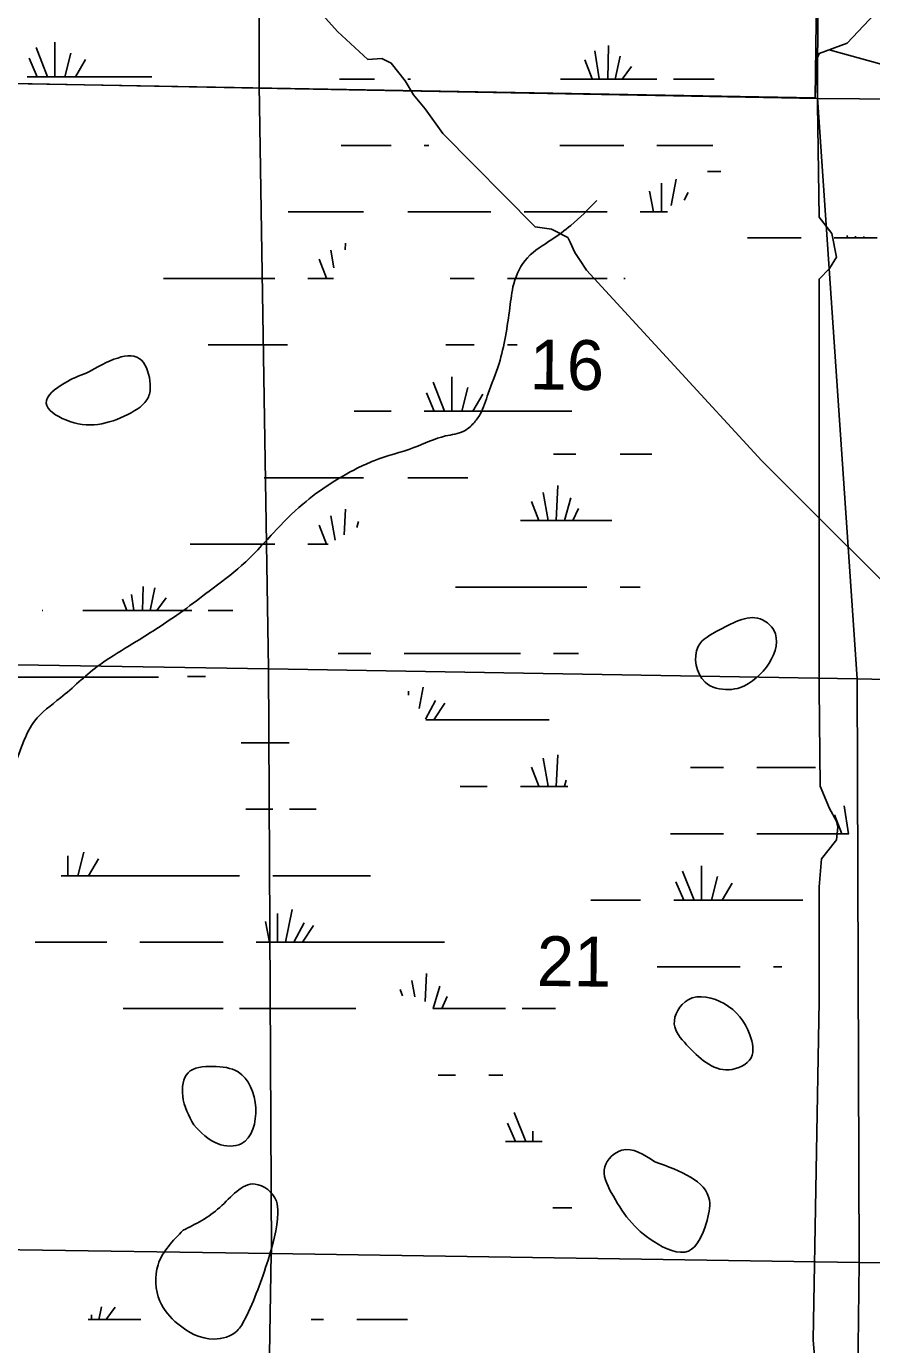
# Model space of a CAD drawing. Extents: x 408847 to 817539, y 923858 to 1151780.
# Drawn here: x 582458 to 590088, y 1023095 to 1034999 of the extents above; entities that cross this region are included whole.
import ezdxf

# ---------------------------------------------------------------- set-up
doc = ezdxf.new("R2010")
doc.units = 0
for name, color, linetype in [('Lakes and Ponds', 7, 'Continuous'), ('Level 43', 7, 'Continuous'), ('Local Roads Paved', 7, 'Continuous'), ('Narrow River Creek and Branch and Slough', 7, 'Continuous'), ('Section Lines', 7, 'Continuous'), ('State Park', 7, 'Continuous'), ('Swamps', 7, 'Continuous')]:
    doc.layers.add(name, color=color, linetype=linetype)

msp = doc.modelspace()

# ---------------------------------------------------------------- linework, layer by layer
at = {"layer": 'Lakes and Ponds'}
for points in [[(582997, 1031866), (582802, 1031778), (582636, 1031597), (582813, 1031445), (583375, 1031495), (583559, 1031651), (583576, 1031767), (583497, 1031983), (582997, 1031866)], [(588714, 1029548), (588522, 1029398), (588585, 1029077), (588798, 1029010), (588904, 1029029), (589204, 1029547), (589103, 1029640), (588714, 1029548)], [(588417, 1025803), (588801, 1025577), (589000, 1025685), (588990, 1025893), (588757, 1026174), (588431, 1026208), (588307, 1025989), (588417, 1025803)], [(583968, 1025080), (584188, 1024908), (584398, 1024909), (584528, 1025232), (584369, 1025557), (584140, 1025607), (583917, 1025549), (583869, 1025340), (583968, 1025080)], [(588130, 1024747), (587833, 1024850), (587679, 1024699), (587738, 1024468), (588122, 1024025), (588435, 1023940), (588594, 1024189), (588624, 1024399), (588130, 1024747)], [(583874, 1024128), (583646, 1023816), (583663, 1023487), (583824, 1023283), (584151, 1023145), (584360, 1023219), (584431, 1023326), (584639, 1023859), (584727, 1024285), (584715, 1024391), (584522, 1024545), (584204, 1024334), (583874, 1024128)]]:
    msp.add_spline(points, degree=3, dxfattribs=at)
at = {"layer": 'Local Roads Paved'}
for points in [[(583335, 1036994), (583683, 1036592), (583820, 1036508), (583958, 1036392), (583979, 1036339), (584327, 1035927), (584591, 1035706), (585266, 1034951)], [(583335, 1036994), (583683, 1036592), (583820, 1036508), (583958, 1036392), (583979, 1036339), (584327, 1035927), (584591, 1035706), (585266, 1034951)], [(592653, 1035968), (592062, 1035904), (591809, 1035820), (591809, 1035820), (591714, 1035788), (590965, 1035598), (590447, 1035397), (590258, 1035334), (590215, 1035218), (589867, 1034848), (589614, 1034753), (589593, 1034701), (589614, 1033275), (589730, 1033127), (589772, 1032916), (589709, 1032811), (589614, 1032716), (589614, 1032705), (589614, 1029020)], [(585266, 1034951), (585541, 1034698), (585667, 1034708), (585752, 1034666), (585878, 1034508), (585952, 1034381), (586058, 1034254), (586216, 1034032), (587050, 1033188), (587197, 1033167), (587345, 1033093), (587366, 1033051), (587408, 1032956), (587451, 1032892), (587514, 1032797), (589097, 1031076), (590659, 1029517)], [(585266, 1034951), (585541, 1034698), (585667, 1034708), (585752, 1034666), (585878, 1034508), (585952, 1034381), (586058, 1034254), (586216, 1034032), (587050, 1033188), (587197, 1033167), (587345, 1033093), (587366, 1033051), (587408, 1032956), (587451, 1032892), (587514, 1032797), (589097, 1031076), (590659, 1029517)], [(589706, 1034788), (590785, 1034489), (591862, 1034215), (592664, 1033995)], [(589614, 1029020), (589624, 1028137), (589709, 1027937), (589772, 1027821), (589783, 1027768), (589772, 1027652), (589762, 1027641)], [(589762, 1027641), (589635, 1027483), (589614, 1027229), (589614, 1026195), (589561, 1023139), (589572, 1022991), (589614, 1022506)]]:
    msp.add_lwpolyline(points, dxfattribs=at)
at = {"layer": 'Narrow River Creek and Branch and Slough'}
msp.add_spline([(578344, 1023366), (578685, 1023341), (578962, 1023402), (579245, 1023485), (579500, 1023572), (579779, 1023651), (580004, 1023741), (580103, 1023850), (580238, 1024045), (580430, 1024259), (580618, 1024431), (580874, 1024657), (581386, 1025130), (581493, 1025235), (581636, 1025518), (581786, 1025867), (581935, 1026208), (582029, 1026506), (582096, 1026797), (582155, 1027119), (582238, 1027391), (582270, 1027751), (582295, 1027981), (582350, 1028297), (582439, 1028556), (582531, 1028724), (582765, 1028935), (583098, 1029218), (583387, 1029406), (583876, 1029725), (584108, 1029899), (584401, 1030130), (584686, 1030423), (584953, 1030685), (585197, 1030866), (585445, 1031008), (585595, 1031076), (585955, 1031195), (586242, 1031300), (586406, 1031344), (586493, 1031413), (586554, 1031497), (586626, 1031682), (586725, 1031954), (586782, 1032199), (586823, 1032461), (586857, 1032673), (586982, 1032910), (587201, 1033074), (587373, 1033201), (587607, 1033426)], degree=3, dxfattribs=at)
at = {"layer": 'Section Lines'}
for p, q in [((584560, 1034469), (584547, 1039763)), ((589612, 1039690), (589600, 1034348)), ((579273, 1034538), (584560, 1034441)), ((584560, 1034469), (584643, 1029196)), ((584560, 1034441), (589600, 1034348)), ((589600, 1034354), (589958, 1029106)), ((589600, 1034348), (594987, 1034298)), ((579348, 1029286), (584643, 1029196)), ((584643, 1029214), (584670, 1023921)), ((584643, 1029196), (589957, 1029106)), ((589957, 1029106), (589976, 1023836)), ((589958, 1029106), (595282, 1029016)), ((579371, 1023999), (584669, 1023917)), ((584669, 1023917), (584568, 1018625)), ((584669, 1023917), (589976, 1023836)), ((589976, 1023836), (589903, 1018532)), ((589976, 1023836), (595213, 1023756))]:
    msp.add_line(p, q, dxfattribs=at)
at = {"layer": 'State Park'}
msp.add_lwpolyline([(589721, 1045058), (589578, 1034352), (573671, 1034637), (573671, 1035240), (557880, 1035240)], dxfattribs=at)
at = {"layer": 'Swamps'}
for p, q in [((582545, 1034807), (582648, 1034544)), ((582545, 1034807), (582648, 1034544)), ((582545, 1034807), (582648, 1034544)), ((582714, 1034855), (582714, 1034544)), ((582714, 1034855), (582714, 1034544)), ((582714, 1034855), (582714, 1034544)), ((587707, 1034523), (587712, 1034827)), ((587707, 1034523), (587712, 1034827)), ((582484, 1034710), (582555, 1034544)), ((582484, 1034710), (582555, 1034544)), ((582484, 1034710), (582555, 1034544)), ((582859, 1034758), (582805, 1034544)), ((582859, 1034758), (582805, 1034544)), ((582859, 1034758), (582805, 1034544)), ((582992, 1034698), (582902, 1034544)), ((582992, 1034698), (582902, 1034544)), ((582992, 1034698), (582902, 1034544)), ((587566, 1034524), (587500, 1034697)), ((587566, 1034524), (587500, 1034697)), ((587628, 1034524), (587589, 1034777)), ((587628, 1034524), (587589, 1034777)), ((587774, 1034523), (587817, 1034729)), ((587774, 1034523), (587817, 1034729)), ((587836, 1034523), (587920, 1034637)), ((587836, 1034523), (587920, 1034637)), ((587400, 1034523), (588150, 1034523)), ((587400, 1034523), (588150, 1034523)), ((585300, 1033923), (585750, 1033923)), ((585300, 1033923), (585750, 1033923)), ((587400, 1033923), (587850, 1033923)), ((587400, 1033923), (587850, 1033923)), ((588083, 1033510), (588120, 1033323)), ((588083, 1033510), (588120, 1033323)), ((588191, 1033582), (588191, 1033323)), ((588191, 1033582), (588191, 1033323)), ((585900, 1033323), (586650, 1033323)), ((585900, 1033323), (586650, 1033323)), ((586950, 1033323), (587400, 1033323)), ((586950, 1033323), (587400, 1033323)), ((587400, 1033323), (587700, 1033323)), ((587400, 1033323), (587700, 1033323)), ((589151, 1033089), (589451, 1033089)), ((589151, 1033089), (589451, 1033089)), ((585166, 1032724), (585100, 1032895)), ((585166, 1032724), (585100, 1032895)), ((586800, 1032723), (587400, 1032723)), ((586800, 1032723), (587400, 1032723)), ((587400, 1032723), (587700, 1032723)), ((587400, 1032723), (587700, 1032723)), ((586299, 1031834), (586299, 1031523)), ((586299, 1031834), (586299, 1031523)), ((586130, 1031786), (586233, 1031523)), ((586130, 1031786), (586233, 1031523)), ((586444, 1031738), (586390, 1031523)), ((586444, 1031738), (586390, 1031523)), ((586069, 1031689), (586140, 1031523)), ((586069, 1031689), (586140, 1031523)), ((586577, 1031677), (586487, 1031524)), ((586577, 1031677), (586487, 1031524)), ((587168, 1030537), (587122, 1030791)), ((587168, 1030537), (587122, 1030791)), ((587168, 1030537), (587122, 1030791)), ((587239, 1030536), (587256, 1030853)), ((587239, 1030536), (587256, 1030853)), ((587239, 1030536), (587256, 1030853)), ((587083, 1030537), (587017, 1030709)), ((587083, 1030537), (587017, 1030709)), ((587083, 1030537), (587017, 1030709)), ((587316, 1030537), (587374, 1030740)), ((587316, 1030537), (587374, 1030740)), ((587316, 1030537), (587374, 1030740)), ((587392, 1030537), (587441, 1030645)), ((587392, 1030537), (587441, 1030645)), ((587392, 1030537), (587441, 1030645)), ((585166, 1030324), (585100, 1030495)), ((585166, 1030324), (585100, 1030495)), ((583574, 1029723), (583617, 1029929)), ((583574, 1029723), (583617, 1029929)), ((583636, 1029723), (583720, 1029837)), ((583636, 1029723), (583720, 1029837)), ((583200, 1029723), (583950, 1029723)), ((583200, 1029723), (583950, 1029723)), ((585867, 1029336), (586917, 1029336)), ((585867, 1029336), (586917, 1029336)), ((585867, 1029336), (586917, 1029336)), ((581850, 1029123), (583200, 1029123)), ((581850, 1029123), (583200, 1029123)), ((583200, 1029123), (583650, 1029123)), ((583200, 1029123), (583650, 1029123)), ((586234, 1028886), (586135, 1028737)), ((586234, 1028886), (586135, 1028737)), ((586234, 1028886), (586135, 1028737)), ((587168, 1028137), (587122, 1028391)), ((587168, 1028137), (587122, 1028391)), ((587168, 1028137), (587122, 1028391)), ((587083, 1028137), (587017, 1028309)), ((587083, 1028137), (587017, 1028309)), ((587083, 1028137), (587017, 1028309)), ((588452, 1028307), (588752, 1028307)), ((588452, 1028307), (588752, 1028307)), ((589880, 1027707), (589841, 1027960)), ((589880, 1027707), (589841, 1027960)), ((589818, 1027708), (589752, 1027880)), ((589818, 1027708), (589752, 1027880)), ((589052, 1027707), (589652, 1027707)), ((589052, 1027707), (589652, 1027707)), ((582976, 1027543), (582923, 1027329)), ((582976, 1027543), (582923, 1027329)), ((583109, 1027483), (583020, 1027329)), ((583109, 1027483), (583020, 1027329)), ((588551, 1027418), (588551, 1027107)), ((588551, 1027418), (588551, 1027107)), ((583933, 1027329), (584383, 1027329)), ((583933, 1027329), (584383, 1027329)), ((588382, 1027369), (588485, 1027107)), ((588382, 1027369), (588485, 1027107)), ((588696, 1027321), (588643, 1027107)), ((588696, 1027321), (588643, 1027107)), ((588322, 1027273), (588392, 1027107)), ((588322, 1027273), (588392, 1027107)), ((588829, 1027261), (588739, 1027107)), ((588829, 1027261), (588739, 1027107)), ((587552, 1027107), (588002, 1027107)), ((587552, 1027107), (588002, 1027107)), ((584724, 1026987), (584724, 1026729)), ((584724, 1026987), (584724, 1026729)), ((584857, 1027024), (584798, 1026729)), ((584857, 1027024), (584798, 1026729)), ((584615, 1026915), (584652, 1026729)), ((584615, 1026915), (584652, 1026729)), ((584965, 1026903), (584871, 1026728)), ((584965, 1026903), (584871, 1026728)), ((585050, 1026879), (584951, 1026730)), ((585050, 1026879), (584951, 1026730)), ((583483, 1026729), (583933, 1026729)), ((583483, 1026729), (583933, 1026729)), ((583933, 1026729), (584233, 1026729)), ((583933, 1026729), (584233, 1026729)), ((584533, 1026729), (586233, 1026729)), ((584533, 1026729), (586233, 1026729)), ((588152, 1026507), (588902, 1026507)), ((588152, 1026507), (588902, 1026507)), ((586131, 1026129), (586189, 1026333)), ((586131, 1026129), (586189, 1026333)), ((586207, 1026129), (586256, 1026238)), ((586207, 1026129), (586256, 1026238)), ((583333, 1026129), (583933, 1026129)), ((583333, 1026129), (583933, 1026129)), ((583933, 1026129), (584233, 1026129)), ((583933, 1026129), (584233, 1026129)), ((584383, 1026129), (585433, 1026129)), ((584383, 1026129), (585433, 1026129)), ((586933, 1026129), (587233, 1026129)), ((586933, 1026129), (587233, 1026129)), ((586802, 1025095), (586873, 1024929)), ((586802, 1025095), (586873, 1024929)), ((583175, 1023320), (583259, 1023434)), ((583175, 1023320), (583259, 1023434)), ((583175, 1023320), (583259, 1023434))]:
    msp.add_line(p, q, dxfattribs=at)
for points in [[(582465, 1034544), (583590, 1034544)], [(582465, 1034544), (583590, 1034544)], [(582465, 1034544), (583590, 1034544)], [(585285, 1034523), (585600, 1034523)], [(585285, 1034523), (585600, 1034523)], [(585900, 1034523), (585925, 1034523)], [(585900, 1034523), (585925, 1034523)], [(587278, 1034523), (587400, 1034523)], [(587278, 1034523), (587400, 1034523)], [(588300, 1034523), (588667, 1034523)], [(588300, 1034523), (588667, 1034523)], [(586050, 1033923), (586091, 1033923)], [(586050, 1033923), (586091, 1033923)], [(587272, 1033923), (587400, 1033923)], [(587272, 1033923), (587400, 1033923)], [(588150, 1033923), (588656, 1033923)], [(588150, 1033923), (588656, 1033923)], [(588324, 1033618), (588277, 1033381)], [(588324, 1033618), (588277, 1033381)], [(588606, 1033689), (588727, 1033689)], [(588606, 1033689), (588727, 1033689)], [(588433, 1033497), (588397, 1033430)], [(588433, 1033497), (588397, 1033430)], [(584820, 1033323), (585500, 1033323)], [(584820, 1033323), (585500, 1033323)], [(588000, 1033323), (588244, 1033323)], [(588000, 1033323), (588244, 1033323)], [(585336, 1032980), (585339, 1033040)], [(585336, 1032980), (585339, 1033040)], [(588967, 1033089), (589151, 1033089)], [(588967, 1033089), (589151, 1033089)], [(589751, 1033089), (590137, 1033089)], [(589751, 1033089), (590137, 1033089)], [(589866, 1033111), (589871, 1033089)], [(589866, 1033111), (589871, 1033089)], [(589942, 1033104), (589942, 1033089)], [(589942, 1033104), (589942, 1033089)], [(590018, 1033100), (590016, 1033089)], [(590018, 1033100), (590016, 1033089)], [(585234, 1032817), (585205, 1032978)], [(585234, 1032817), (585205, 1032978)], [(583697, 1032723), (584700, 1032723)], [(583697, 1032723), (584700, 1032723)], [(585000, 1032723), (585229, 1032723)], [(585000, 1032723), (585229, 1032723)], [(586284, 1032723), (586500, 1032723)], [(586284, 1032723), (586500, 1032723)], [(587850, 1032723), (587863, 1032723)], [(587850, 1032723), (587863, 1032723)], [(584100, 1032123), (584814, 1032123)], [(584100, 1032123), (584814, 1032123)], [(586243, 1032123), (586500, 1032123)], [(586243, 1032123), (586500, 1032123)], [(586800, 1032123), (586888, 1032123)], [(586800, 1032123), (586888, 1032123)], [(585418, 1031523), (585750, 1031523)], [(585418, 1031523), (585750, 1031523)], [(586050, 1031523), (587382, 1031523)], [(586050, 1031523), (587382, 1031523)], [(587215, 1031136), (587417, 1031136)], [(587215, 1031136), (587417, 1031136)], [(587215, 1031136), (587417, 1031136)], [(587817, 1031136), (588105, 1031136)], [(587817, 1031136), (588105, 1031136)], [(587817, 1031136), (588105, 1031136)], [(584603, 1030923), (585500, 1030923)], [(584603, 1030923), (585500, 1030923)], [(585900, 1030923), (586442, 1030923)], [(585900, 1030923), (586442, 1030923)], [(585326, 1030408), (585339, 1030640)], [(585326, 1030408), (585339, 1030640)], [(585244, 1030360), (585205, 1030578)], [(585244, 1030360), (585205, 1030578)], [(585442, 1030475), (585457, 1030527)], [(585442, 1030475), (585457, 1030527)], [(586917, 1030536), (587742, 1030536)], [(586917, 1030536), (587742, 1030536)], [(586917, 1030536), (587742, 1030536)], [(583935, 1030323), (584700, 1030323)], [(583935, 1030323), (584700, 1030323)], [(585000, 1030323), (585182, 1030323)], [(585000, 1030323), (585182, 1030323)], [(583507, 1029723), (583511, 1029942)], [(583507, 1029723), (583511, 1029942)], [(586332, 1029936), (587517, 1029936)], [(586332, 1029936), (587517, 1029936)], [(586332, 1029936), (587517, 1029936)], [(587817, 1029936), (587998, 1029936)], [(587817, 1029936), (587998, 1029936)], [(587817, 1029936), (587998, 1029936)], [(583366, 1029724), (583327, 1029826)], [(583366, 1029724), (583327, 1029826)], [(583428, 1029724), (583406, 1029867)], [(583428, 1029724), (583406, 1029867)], [(582600, 1029723), (582606, 1029723)], [(582600, 1029723), (582606, 1029723)], [(582967, 1029723), (583200, 1029723)], [(582967, 1029723), (583200, 1029723)], [(584100, 1029723), (584321, 1029723)], [(584100, 1029723), (584321, 1029723)], [(585273, 1029336), (585567, 1029336)], [(585273, 1029336), (585567, 1029336)], [(585273, 1029336), (585567, 1029336)], [(587217, 1029336), (587443, 1029336)], [(587217, 1029336), (587443, 1029336)], [(587217, 1029336), (587443, 1029336)], [(583911, 1029129), (583933, 1029129)], [(583911, 1029129), (583933, 1029129)], [(583933, 1029129), (584074, 1029129)], [(583933, 1029129), (584074, 1029129)], [(585908, 1028995), (585908, 1028959)], [(585908, 1028995), (585908, 1028959)], [(585908, 1028995), (585908, 1028959)], [(586041, 1029031), (586003, 1028838)], [(586041, 1029031), (586003, 1028838)], [(586041, 1029031), (586003, 1028838)], [(586150, 1028910), (586061, 1028744)], [(586150, 1028910), (586061, 1028744)], [(586150, 1028910), (586061, 1028744)], [(586065, 1028736), (587177, 1028736)], [(586065, 1028736), (587177, 1028736)], [(586065, 1028736), (587177, 1028736)], [(584398, 1028529), (584831, 1028529)], [(584398, 1028529), (584831, 1028529)], [(587239, 1028136), (587254, 1028421)], [(587239, 1028136), (587254, 1028421)], [(587239, 1028136), (587254, 1028421)], [(589052, 1028307), (589582, 1028307)], [(589052, 1028307), (589582, 1028307)], [(589052, 1028307), (589582, 1028307)], [(586374, 1028136), (586617, 1028136)], [(586374, 1028136), (586617, 1028136)], [(586374, 1028136), (586617, 1028136)], [(586917, 1028136), (587345, 1028136)], [(586917, 1028136), (587345, 1028136)], [(586917, 1028136), (587345, 1028136)], [(587316, 1028137), (587331, 1028193)], [(587316, 1028137), (587331, 1028193)], [(587316, 1028137), (587331, 1028193)], [(584440, 1027929), (584683, 1027929)], [(584440, 1027929), (584683, 1027929)], [(584833, 1027929), (585075, 1027929)], [(584833, 1027929), (585075, 1027929)], [(588271, 1027707), (588752, 1027707)], [(588271, 1027707), (588752, 1027707)], [(589652, 1027707), (589881, 1027707)], [(589652, 1027707), (589881, 1027707)], [(582831, 1027508), (582831, 1027329)], [(582831, 1027508), (582831, 1027329)], [(582773, 1027329), (583933, 1027329)], [(582773, 1027329), (583933, 1027329)], [(584683, 1027329), (585565, 1027329)], [(584683, 1027329), (585565, 1027329)], [(588302, 1027107), (589467, 1027107)], [(588302, 1027107), (589467, 1027107)], [(582536, 1026729), (583183, 1026729)], [(582536, 1026729), (583183, 1026729)], [(589202, 1026507), (589277, 1026507)], [(589202, 1026507), (589277, 1026507)], [(585964, 1026234), (585937, 1026383)], [(585964, 1026234), (585937, 1026383)], [(586058, 1026194), (586071, 1026445)], [(586058, 1026194), (586071, 1026445)], [(585853, 1026246), (585833, 1026301)], [(585853, 1026246), (585833, 1026301)], [(586127, 1026129), (586783, 1026129)], [(586127, 1026129), (586783, 1026129)], [(586176, 1025529), (586333, 1025529)], [(586176, 1025529), (586333, 1025529)], [(586633, 1025529), (586758, 1025529)], [(586633, 1025529), (586758, 1025529)], [(586862, 1025192), (586965, 1024929)], [(586862, 1025192), (586965, 1024929)], [(586783, 1024929), (587114, 1024929)], [(586783, 1024929), (587114, 1024929)], [(587031, 1025022), (587031, 1024929)], [(587031, 1025022), (587031, 1024929)], [(587210, 1024329), (587383, 1024329)], [(587210, 1024329), (587383, 1024329)], [(583113, 1023320), (583137, 1023437)], [(583113, 1023320), (583137, 1023437)], [(583113, 1023320), (583137, 1023437)], [(583015, 1023321), (583490, 1023321)], [(583015, 1023321), (583490, 1023321)], [(583015, 1023321), (583490, 1023321)], [(583046, 1023321), (583047, 1023365)], [(583046, 1023321), (583047, 1023365)], [(583046, 1023321), (583047, 1023365)], [(585030, 1023321), (585140, 1023321)], [(585030, 1023321), (585140, 1023321)], [(585030, 1023321), (585140, 1023321)], [(585440, 1023321), (585897, 1023321)], [(585440, 1023321), (585897, 1023321)], [(585440, 1023321), (585897, 1023321)]]:
    msp.add_lwpolyline(points, dxfattribs=at)

# ---------------------------------------------------------------- texts
at = {"layer": 'Level 43'}
for s, p in [('16', (587000, 1031721)), ('21', (587064, 1026334))]:
    msp.add_text(s, height=450, rotation=359.379, dxfattribs=at).set_placement(p)

doc.saveas('drawing.dxf')
